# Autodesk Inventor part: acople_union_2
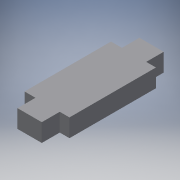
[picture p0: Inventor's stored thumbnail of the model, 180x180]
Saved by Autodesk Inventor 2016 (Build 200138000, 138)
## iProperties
Created: 2017-06
Part Number: acople_union_2
Material: Generic
Document SubType Name: Modeling
Designer: laboratorioesan
Density: 1 g/cm^3
Appearance: Default
Author: laboratorioesan
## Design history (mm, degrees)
sketch "Sketch1"
  geometry: L1 (0, 0)-(-25, 0) reference; L2 (0, 0)-(0, 18.5) reference; L3 (-25, 18.5)-(0, 18.5) reference; L4 (-25, 0)-(-25, 18.5) reference; L5 (10, 107.5)-(10, 18.5) reference; L6 (-46.75, 18.5)-(-36.25, 18.5) reference; L7 (-36.25, 18.5)-(10, 18.5); L8 (10, 18.5)-(10, 107.5); L9 (10, 107.5)-(-36.25, 107.5); L10 (-36.25, 107.5)-(-36.25, 18.5); L11 (-25, 107.5)-(0, 107.5); L12 (0, 107.5)-(0, 125.5); L13 (0, 125.5)-(-25, 125.5); L14 (-25, 125.5)-(-25, 107.5)
  constraints: 16 end point, 4 parallel, 2 horizontal, 2 perpendicular, 1 point on line
  dimensions: "d0" = 18 distance of L11.end L12.end
extrude "Extrusion1" new body sketch "Sketch1" distance "d1" = 18.5; taper "d2" = 0 deg
body "Solid1"
node "Reference1"
node "Reference2"
node "Reference3"
